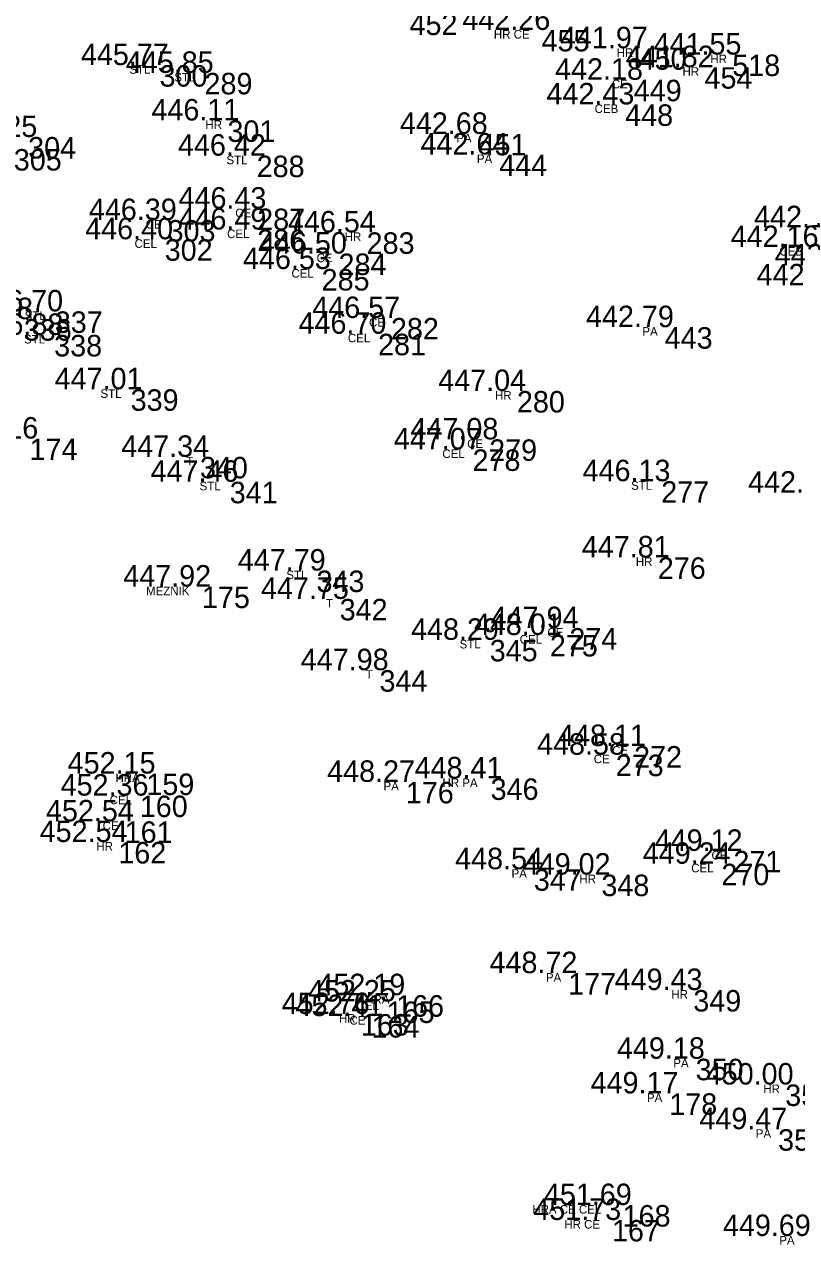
# Model space of a CAD drawing. Extents: x -639390 to -639075, y -1138747 to -1138358.
# Drawn here: x -639228.45 to -639201.49, y -1138684.31 to -1138641.7 of the extents above; entities that cross this region are included whole.
import ezdxf

# ---------------------------------------------------------------- set-up
doc = ezdxf.new("R2010")
doc.units = 0
for name, color, linetype in [('Vrstva 11', 7, 'Continuous'), ('Vrstva 12', 7, 'Continuous'), ('Vrstva 13', 7, 'Continuous'), ('Vrstva 57', 7, 'Continuous')]:
    doc.layers.add(name, color=color, linetype=linetype)

msp = doc.modelspace()

# ---------------------------------------------------------------- linework, layer by layer
at = {"layer": 'Vrstva 11'}
for p, q in [((-639210.67, -1138641.89), (-639210.67, -1138641.89)), ((-639207.28, -1138642.53), (-639207.28, -1138642.53)), ((-639224.01, -1138643.12), (-639224.01, -1138643.12)), ((-639204.01, -1138642.75), (-639204.01, -1138642.75)), ((-639222.44, -1138643.39), (-639222.44, -1138643.39)), ((-639204.98, -1138643.19), (-639204.98, -1138643.19)), ((-639207.45, -1138643.63), (-639207.45, -1138643.63)), ((-639207.75, -1138644.49), (-639207.75, -1138644.49)), ((-639221.64, -1138645.05), (-639221.64, -1138645.05)), ((-639212.87, -1138645.52), (-639212.87, -1138645.52)), ((-639220.62, -1138646.28), (-639220.62, -1138646.28)), ((-639212.15, -1138646.24), (-639212.15, -1138646.24)), ((-639220.6, -1138648.13), (-639220.6, -1138648.13)), ((-639223.73, -1138648.53), (-639223.73, -1138648.53)), ((-639220.6, -1138648.86), (-639220.6, -1138648.86)), ((-639216.78, -1138648.96), (-639216.78, -1138648.96)), ((-639223.83, -1138649.2), (-639223.83, -1138649.2)), ((-639217.76, -1138649.7), (-639217.76, -1138649.7)), ((-639218.35, -1138650.24), (-639218.35, -1138650.24)), ((-639227.67, -1138651.72), (-639227.67, -1138651.72)), ((-639215.93, -1138651.95), (-639215.93, -1138651.95)), ((-639216.38, -1138652.5), (-639216.38, -1138652.5)), ((-639206.37, -1138652.27), (-639206.37, -1138652.27)), ((-639227.69, -1138652.54), (-639227.69, -1138652.54)), ((-639225.02, -1138654.44), (-639225.02, -1138654.44)), ((-639211.53, -1138654.5), (-639211.53, -1138654.5)), ((-639212.5, -1138656.19), (-639212.5, -1138656.19)), ((-639213.08, -1138656.54), (-639213.08, -1138656.54)), ((-639222.6, -1138656.8), (-639222.6, -1138656.8)), ((-639221.56, -1138657.67), (-639221.56, -1138657.67)), ((-639206.49, -1138657.65), (-639206.49, -1138657.65)), ((-639206.61, -1138660.31), (-639206.61, -1138660.31)), ((-639218.53, -1138660.77), (-639218.53, -1138660.77)), ((-639222.53, -1138661.33), (-639222.53, -1138661.33)), ((-639217.72, -1138661.76), (-639217.72, -1138661.76)), ((-639210.38, -1138663.02), (-639210.38, -1138663.02)), ((-639209.7, -1138662.78), (-639209.7, -1138662.78)), ((-639212.48, -1138663.19), (-639212.48, -1138663.19)), ((-639216.33, -1138664.25), (-639216.33, -1138664.25)), ((-639207.44, -1138666.9), (-639207.44, -1138666.9)), ((-639208.08, -1138667.2), (-639208.08, -1138667.2)), ((-639224.47, -1138667.86), (-639224.47, -1138667.86)), ((-639215.41, -1138668.15), (-639215.41, -1138668.15)), ((-639212.45, -1138668.03), (-639212.45, -1138668.03)), ((-639224.7, -1138668.63), (-639224.7, -1138668.63)), ((-639225.23, -1138669.53), (-639225.23, -1138669.53)), ((-639225.45, -1138670.25), (-639225.45, -1138670.25)), ((-639203.97, -1138670.56), (-639203.97, -1138670.56)), ((-639210.94, -1138671.2), (-639210.94, -1138671.2)), ((-639204.39, -1138671.01), (-639204.39, -1138671.01)), ((-639208.58, -1138671.39), (-639208.58, -1138671.39)), ((-639209.74, -1138674.83), (-639209.74, -1138674.83)), ((-639205.37, -1138675.42), (-639205.37, -1138675.42)), ((-639216.08, -1138675.82), (-639216.08, -1138675.82)), ((-639215.75, -1138675.6), (-639215.75, -1138675.6)), ((-639216.98, -1138676.26), (-639216.98, -1138676.26)), ((-639216.61, -1138676.33), (-639216.61, -1138676.33)), ((-639205.29, -1138677.82), (-639205.29, -1138677.82)), ((-639202.16, -1138678.72), (-639202.16, -1138678.72)), ((-639206.21, -1138679.03), (-639206.21, -1138679.03)), ((-639202.41, -1138680.28), (-639202.41, -1138680.28)), ((-639207.84, -1138682.93), (-639207.84, -1138682.93)), ((-639208.21, -1138683.45), (-639208.21, -1138683.45)), ((-639201.59, -1138684.01), (-639201.59, -1138684.01))]:
    msp.add_line(p, q, dxfattribs=at)

# ---------------------------------------------------------------- texts
at = {"layer": 'Vrstva 12'}
for s, p in [('442.26 ', (-639213.156, -1138641.89)), ('441.97 ', (-639209.749, -1138642.53)), ('441.55 ', (-639206.48, -1138642.75)), ('445.77 ', (-639226.479, -1138643.12)), ('445.85 ', (-639224.91, -1138643.39)), ('441.82 ', (-639207.449, -1138643.19)), ('442.18 ', (-639209.919, -1138643.63)), ('442.43 ', (-639210.219, -1138644.49)), ('446.11 ', (-639224.015, -1138645.05)), ('442.68 ', (-639215.339, -1138645.52)), ('446.25 ', (-639231.07, -1138645.63)), ('446.42 ', (-639223.089, -1138646.28)), ('442.64 ', (-639214.619, -1138646.24)), ('446.43 ', (-639223.069, -1138648.13)), ('446.39 ', (-639226.199, -1138648.53)), ('446.49 ', (-639223.069, -1138648.86)), ('446.54 ', (-639219.249, -1138648.96)), ('442.10 ', (-639202.969, -1138648.78)), ('446.40 ', (-639226.329, -1138649.2)), ('446.50 ', (-639220.259, -1138649.7)), ('442.16 ', (-639203.786, -1138649.47)), ('446.53 ', (-639220.819, -1138650.24)), ('442.20 ', (-639202.249, -1138650.11)), ('442.18 ', (-639202.879, -1138650.81)), ('446.68 ', (-639231.219, -1138651.99)), ('446.70 ', (-639230.169, -1138651.72)), ('446.57 ', (-639218.399, -1138651.95)), ('442.79 ', (-639208.839, -1138652.27)), ('446.88 ', (-639230.159, -1138652.54)), ('446.70 ', (-639218.879, -1138652.5)), ('447.01 ', (-639227.395, -1138654.44)), ('447.04 ', (-639213.999, -1138654.5)), ('447.16 ', (-639231.036, -1138656.16)), ('447.08 ', (-639214.969, -1138656.19)), ('447.07 ', (-639215.549, -1138656.54)), ('447.34 ', (-639225.069, -1138656.8)), ('447.46 ', (-639224.046, -1138657.67)), ('446.13 ', (-639208.959, -1138657.65)), ('442.94 ', (-639203.179, -1138658.05)), ('447.81 ', (-639208.985, -1138660.31)), ('447.79 ', (-639220.999, -1138660.77)), ('447.92 ', (-639224.999, -1138661.33)), ('447.75 ', (-639220.19, -1138661.76)), ('448.01 ', (-639212.755, -1138663.02)), ('447.94 ', (-639212.169, -1138662.78)), ('448.29 ', (-639214.949, -1138663.19)), ('447.98 ', (-639218.799, -1138664.25)), ('448.11 ', (-639209.815, -1138666.9)), ('448.58 ', (-639210.549, -1138667.2)), ('452.15 ', (-639226.94, -1138667.86)), ('448.27 ', (-639217.879, -1138668.15)), ('448.41 ', (-639214.825, -1138668.03)), ('452.36 ', (-639227.186, -1138668.63)), ('452.54 ', (-639227.699, -1138669.53)), ('452.54 ', (-639227.919, -1138670.25)), ('449.12 ', (-639206.439, -1138670.56)), ('449.24 ', (-639206.859, -1138671.01)), ('448.54 ', (-639213.409, -1138671.2)), ('449.02 ', (-639211.049, -1138671.39)), ('448.72 ', (-639212.209, -1138674.83)), ('449.43 ', (-639207.839, -1138675.42)), ('452.25 ', (-639218.55, -1138675.82)), ('452.19 ', (-639218.219, -1138675.6)), ('452.76 ', (-639219.466, -1138676.26)), ('452.41 ', (-639218.985, -1138676.33)), ('449.18 ', (-639207.759, -1138677.82)), ('450.00 ', (-639204.659, -1138678.72)), ('449.17 ', (-639208.679, -1138679.03)), ('449.47 ', (-639204.879, -1138680.28)), ('451.69 ', (-639210.309, -1138682.93)), ('451.73 ', (-639210.679, -1138683.45)), ('449.69 ', (-639204.059, -1138684.01))]:
    msp.add_text(s, height=0.75, dxfattribs=at).set_placement(p)
at = {"layer": 'Vrstva 13'}
for s, p in [(' 452', (-639215.28, -1138642.07)), (' 455', (-639210.67, -1138642.64)), (' 450', (-639207.28, -1138643.28)), (' 300', (-639224.01, -1138643.87)), (' 518', (-639204.01, -1138643.5)), (' 289', (-639222.44, -1138644.14)), (' 454', (-639204.98, -1138643.94)), (' 449', (-639207.45, -1138644.38)), (' 448', (-639207.75, -1138645.24)), (' 301', (-639221.64, -1138645.8)), (' 304', (-639228.6, -1138646.38)), (' 451', (-639212.87, -1138646.27)), (' 305', (-639229.1, -1138646.8)), (' 288', (-639220.62, -1138647.03)), (' 444', (-639212.15, -1138646.99)), (' 287', (-639220.6, -1138648.88)), (' 303', (-639223.73, -1138649.28)), (' 286', (-639220.6, -1138649.61)), (' 283', (-639216.78, -1138649.71)), (' 302', (-639223.83, -1138649.95)), (' 284', (-639217.76, -1138650.45)), (' 285', (-639218.35, -1138650.99)), (' 336', (-639228.75, -1138652.74)), (' 337', (-639227.67, -1138652.47)), (' 282', (-639215.93, -1138652.7)), (' 338', (-639227.69, -1138653.29)), (' 281', (-639216.38, -1138653.25)), (' 443', (-639206.37, -1138653.02)), (' 339', (-639225.02, -1138655.19)), (' 280', (-639211.53, -1138655.25)), (' 174', (-639228.55, -1138656.91)), (' 279', (-639212.5, -1138656.94)), (' 340', (-639222.6, -1138657.55)), (' 278', (-639213.08, -1138657.29)), (' 277', (-639206.49, -1138658.4)), (' 341', (-639221.56, -1138658.42)), (' 276', (-639206.61, -1138661.06)), (' 343', (-639218.53, -1138661.52)), (' 175', (-639222.53, -1138662.08)), (' 342', (-639217.72, -1138662.51)), (' 345', (-639212.48, -1138663.94)), (' 275', (-639210.38, -1138663.77)), (' 274', (-639209.7, -1138663.53)), (' 344', (-639216.33, -1138665)), (' 272', (-639207.44, -1138667.65)), (' 273', (-639208.08, -1138667.95)), (' 159', (-639224.47, -1138668.61)), (' 176', (-639215.41, -1138668.9)), (' 346', (-639212.45, -1138668.78)), (' 160', (-639224.7, -1138669.38)), (' 161', (-639225.23, -1138670.28)), (' 162', (-639225.45, -1138671)), (' 271', (-639203.97, -1138671.31)), (' 347', (-639210.94, -1138671.95)), (' 270', (-639204.39, -1138671.76)), (' 348', (-639208.58, -1138672.14)), (' 177', (-639209.74, -1138675.58)), (' 349', (-639205.37, -1138676.17)), (' 165', (-639216.08, -1138676.57)), (' 166', (-639215.75, -1138676.35)), (' 163', (-639216.98, -1138677.01)), (' 164', (-639216.61, -1138677.08)), (' 350', (-639205.29, -1138678.57)), (' 352', (-639202.16, -1138679.47)), (' 178', (-639206.21, -1138679.78)), (' 351', (-639202.41, -1138681.03)), (' 168', (-639207.84, -1138683.68)), (' 167', (-639208.21, -1138684.2))]:
    msp.add_text(s, height=0.75, dxfattribs=at).set_placement(p)
at = {"layer": 'Vrstva 57'}
for s, p in [('HR CE', (-639212.057, -1138642.19)), ('HR', (-639207.769, -1138642.83)), ('STL', (-639224.785, -1138643.42)), ('HR', (-639204.499, -1138643.05)), ('STL', (-639223.215, -1138643.69)), ('HR', (-639205.469, -1138643.49)), ('CE', (-639207.938, -1138643.93)), ('CEB', (-639208.539, -1138644.79)), ('HR', (-639222.129, -1138645.35)), ('PA', (-639213.37, -1138645.82)), ('STL', (-639221.395, -1138646.58)), ('PA', (-639212.65, -1138646.54)), ('CE', (-639221.088, -1138648.43)), ('CE', (-639224.218, -1138648.83)), ('CEL', (-639221.375, -1138649.16)), ('HR', (-639217.269, -1138649.26)), ('CEL', (-639224.605, -1138649.5)), ('CEB', (-639202.089, -1138649.77)), ('CE', (-639218.248, -1138650)), ('CEL', (-639219.125, -1138650.54)), ('STL', (-639228.445, -1138652.02)), ('CE', (-639216.417, -1138652.25)), ('CEL', (-639217.155, -1138652.8)), ('PA', (-639206.87, -1138652.57)), ('STL', (-639228.465, -1138652.84)), ('STL', (-639225.795, -1138654.74)), ('HR', (-639212.019, -1138654.8)), ('CE', (-639212.988, -1138656.49)), ('CEL', (-639213.855, -1138656.84)), ('T', (-639222.8, -1138657.1)), ('STL', (-639222.335, -1138657.97)), ('STL', (-639207.265, -1138657.95)), ('HR', (-639207.099, -1138660.61)), ('STL', (-639219.305, -1138661.07)), ('MEZNIK', (-639224.205, -1138661.63)), ('T', (-639217.92, -1138662.06)), ('CEL', (-639211.155, -1138663.32)), ('CE', (-639210.188, -1138663.08)), ('STL', (-639213.255, -1138663.49)), ('T', (-639216.53, -1138664.55)), ('CE', (-639207.927, -1138667.2)), ('CE', (-639208.568, -1138667.5)), ('HRA', (-639225.27, -1138668.16)), ('PA', (-639215.91, -1138668.45)), ('HR PA', (-639213.85, -1138668.33)), ('CEL', (-639225.475, -1138668.93)), ('CE', (-639225.718, -1138669.83)), ('HR', (-639225.939, -1138670.55)), ('CE', (-639204.458, -1138670.86)), ('PA', (-639211.44, -1138671.5)), ('CEL', (-639205.165, -1138671.31)), ('HR', (-639209.069, -1138671.69)), ('PA', (-639210.24, -1138675.13)), ('HR', (-639205.859, -1138675.72)), ('CEL', (-639216.855, -1138676.12)), ('HRA', (-639216.55, -1138675.9)), ('HR', (-639217.469, -1138676.56)), ('CE', (-639217.098, -1138676.63)), ('PA', (-639205.79, -1138678.12)), ('HR', (-639202.649, -1138679.02)), ('PA', (-639206.71, -1138679.33)), ('PA', (-639202.91, -1138680.58)), ('HRA CE CEL', (-639210.715, -1138683.23)), ('HR CE', (-639209.598, -1138683.75)), ('PA', (-639202.09, -1138684.31))]:
    msp.add_text(s, height=0.3, dxfattribs=at).set_placement(p)

doc.saveas('drawing.dxf')
